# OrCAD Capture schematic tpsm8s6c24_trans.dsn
size E
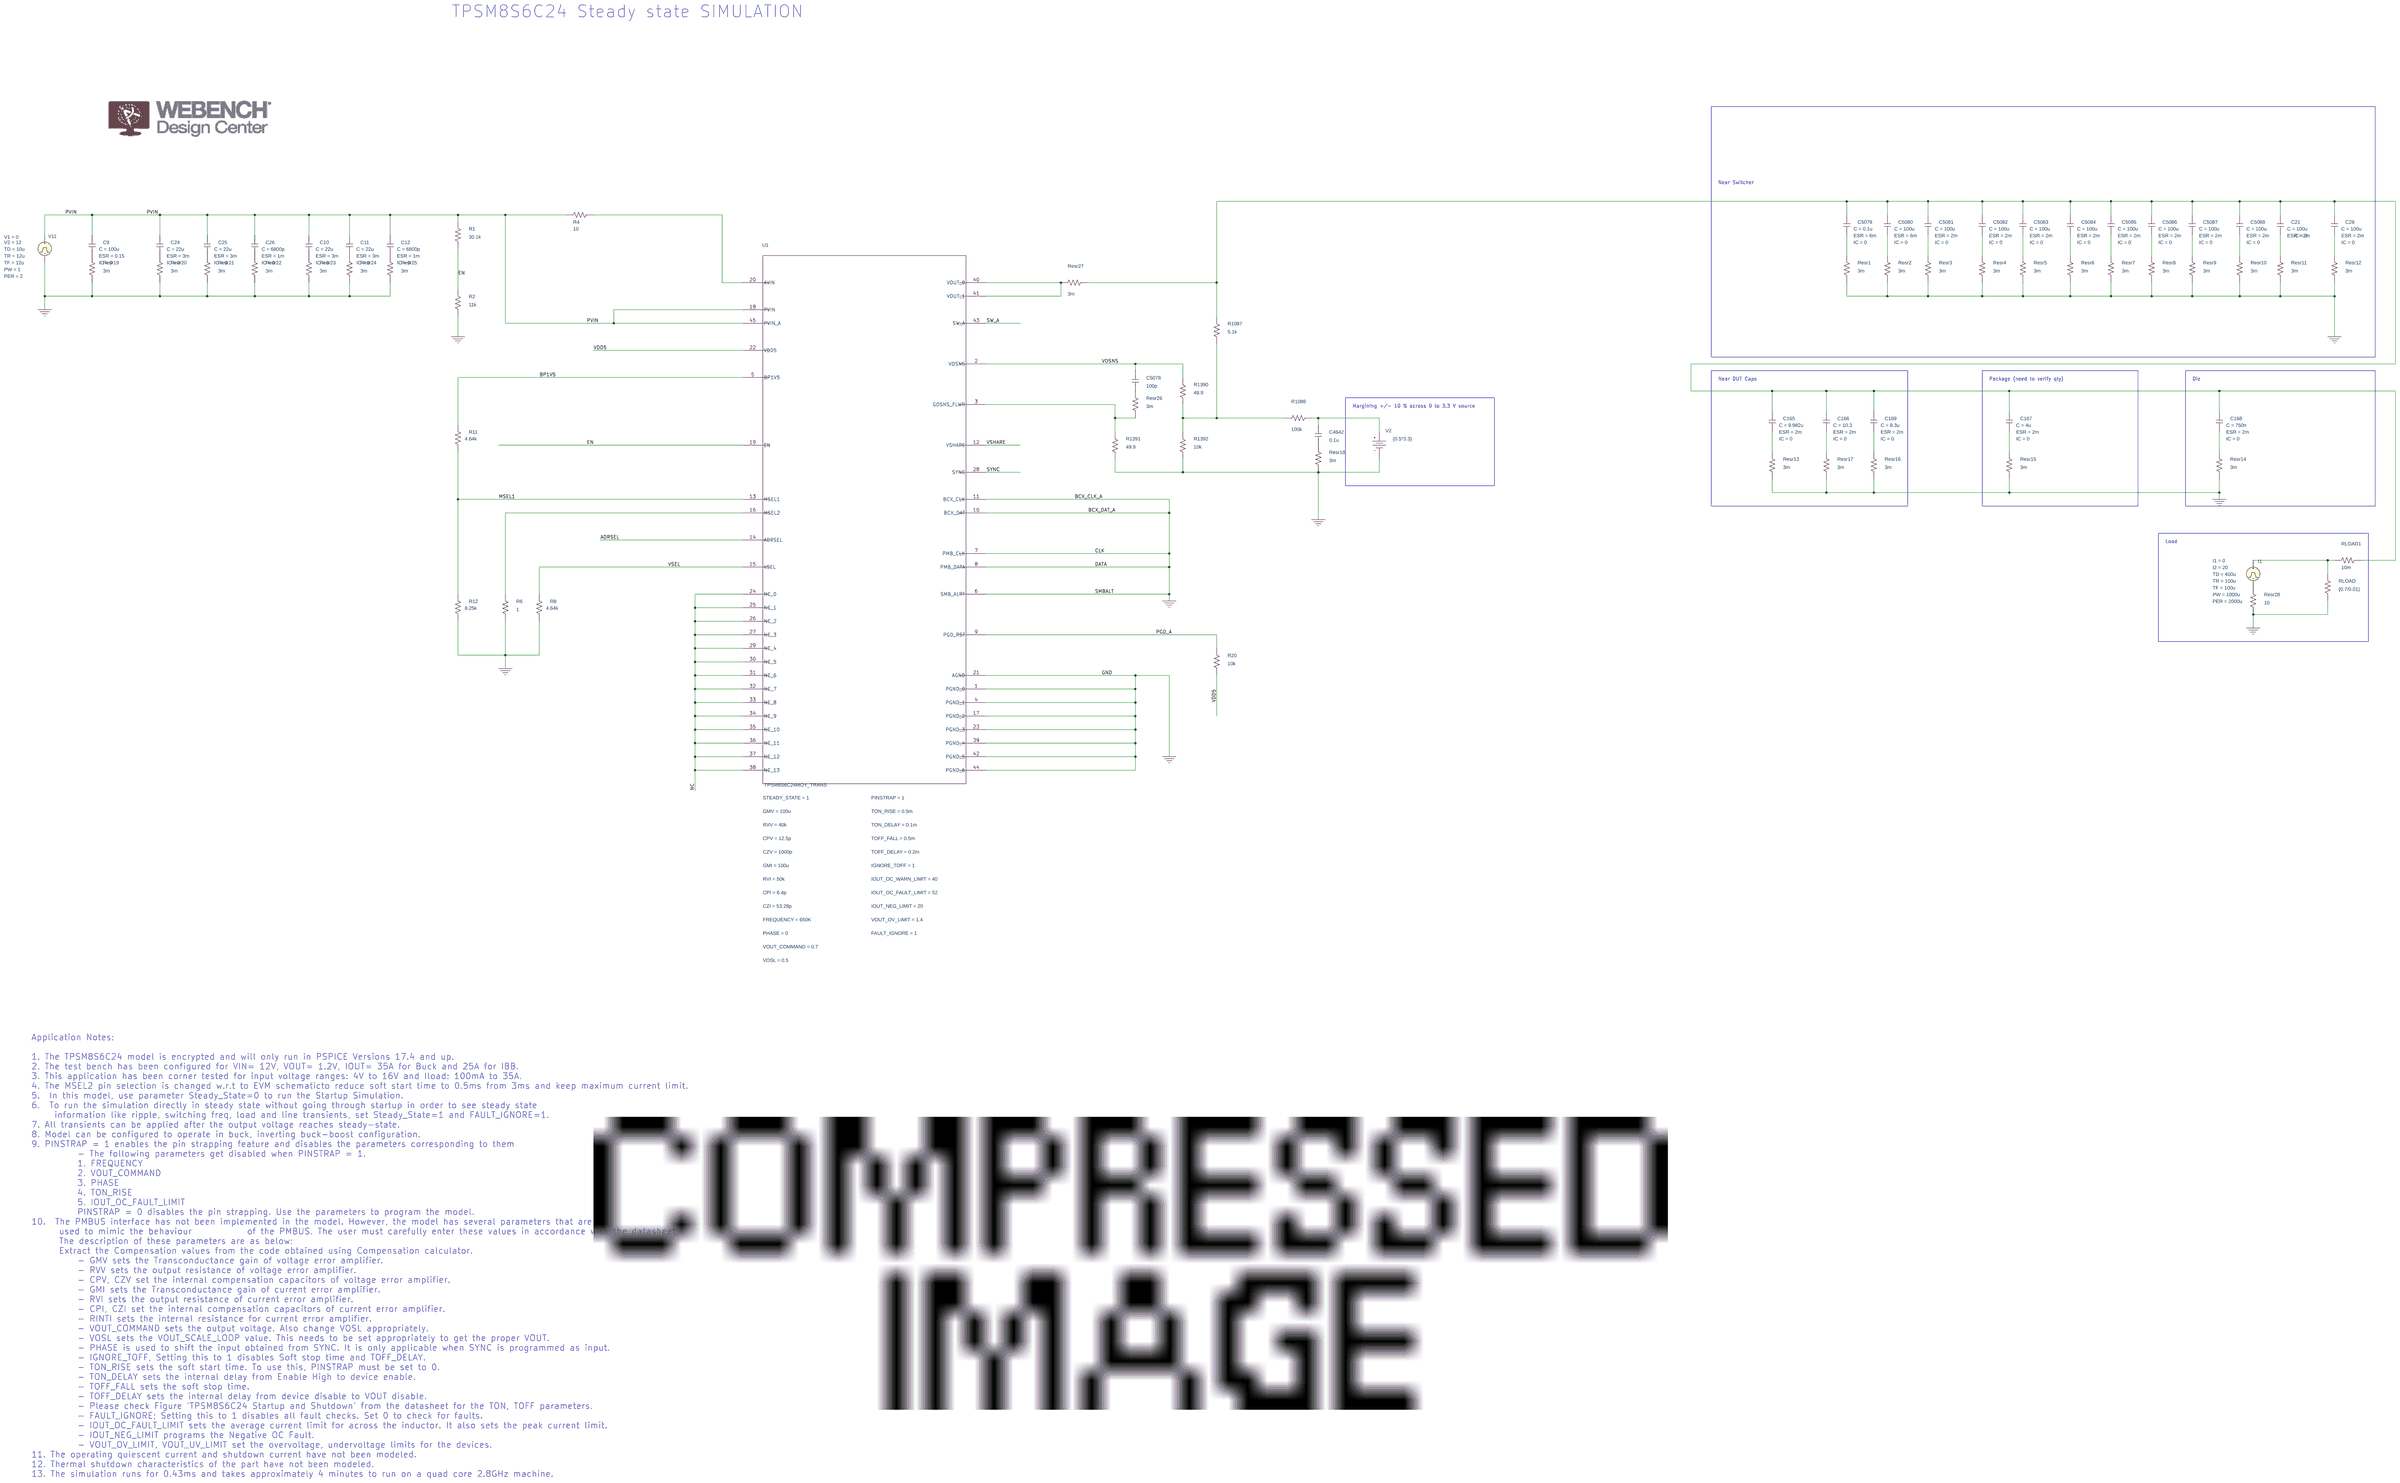
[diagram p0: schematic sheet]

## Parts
C9  100u  [cap196]
C10  100u  [cap196]
C11  100u  [cap196]
C12  100u  [cap196]
C21  100u  [cap196]
C24  100u  [cap196]
C25  100u  [cap196]
C26  100u  [cap196]
C28  100u  [cap196]
C165  100u  [cap196]
C166  100u  [cap196]
C167  100u  [cap196]
C168  100u  [cap196]
C169  100u  [cap196]
C4642  0.1u  [cap196]
C5078  100p  [cap196]
C5079  100u  [cap196]
C5080  100u  [cap196]
C5081  100u  [cap196]
C5082  100u  [cap196]
C5083  100u  [cap196]
C5084  100u  [cap196]
C5085  100u  [cap196]
C5086  100u  [cap196]
C5087  100u  [cap196]
C5088  100u  [cap196]
I1  IPULSE
R1  30.1k  [AXRC05]
R2  11k  [AXRC05]
R4  10  [AXRC05]
R6  1  [AXRC05]
R8  4.64k  [AXRC05]
R11  4.64k  [AXRC05]
R12  8.25k  [AXRC05]
R20  10k  [AXRC05]
R1087  5.1k  [AXRC05]
R1088  100k  [AXRC05]
R1390  49.9  [AXRC05]
R1391  49.9  [AXRC05]
R1392  10k  [AXRC05]
Resr1  3m  [AXRC05]
Resr2  3m  [AXRC05]
Resr3  3m  [AXRC05]
Resr4  3m  [AXRC05]
Resr5  3m  [AXRC05]
Resr6  3m  [AXRC05]
Resr7  3m  [AXRC05]
Resr8  3m  [AXRC05]
Resr9  3m  [AXRC05]
Resr10  3m  [AXRC05]
Resr11  3m  [AXRC05]
Resr12  3m  [AXRC05]
Resr13  3m  [AXRC05]
Resr14  3m  [AXRC05]
Resr15  3m  [AXRC05]
Resr16  3m  [AXRC05]
Resr17  3m  [AXRC05]
Resr18  3m  [AXRC05]
Resr19  3m  [AXRC05]
Resr20  3m  [AXRC05]
Resr21  3m  [AXRC05]
Resr22  3m  [AXRC05]
Resr23  3m  [AXRC05]
Resr24  3m  [AXRC05]
Resr25  3m  [AXRC05]
Resr26  3m  [AXRC05]
Resr27  3m  [AXRC05]
Resr28  10  [AXRC05]
RLOAD  {0.7/0.01}  [AXRC05]
RLOAD1  10m  [AXRC05]
U1  Value  [MOY0045A-MFG]
V2  VDC
V11  VPULSE

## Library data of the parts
C9 = C: ESR: 0.15; IC: 0
C10 C11 C24 C25 = C: C: 22u; ESR: 3m; IC: 0
C12 C26 = C: C: 6800p; ESR: 1m; IC: 0
C21 C28 C5081-C5088 = C: ESR: 2m; IC: 0
C165 = C: C: 9.982u; ESR: 2m; IC: 0
C166 = C: C: 10.3; ESR: 2m; IC: 0
C167 = C: C: 4u; ESR: 2m; IC: 0
C168 = C: C: 750n; ESR: 2m; IC: 0
C169 = C: C: 8.3u; ESR: 2m; IC: 0
C4642 C5078 = C
C5079 = C: C: 0.1u; ESR: 6m; IC: 0
C5080 = C: ESR: 6m; IC: 0
I1 = IPULSE: I1: 0; I2: 20; PER: 2000u; PW: 1000u; TD: 400u; TF: 100u; TR: 100u
R1 R2 R4 R6 R8 R11 R12 R20 R1087 R1088 R1390-R1392 Resr1-Resr28 RLOAD RLOAD1 = R
U1 = TPSM8S6C24SMOY_TRANS: < Value >: TPSM8S6C24MOY_TRANS; CPI: 6.4p; CPV: 12.5p; CSGAIN: 6.155M; CZI: 53.28p; CZV: 1000p; FAULT_IGNORE: 1; FREQUENCY: 650K; GM: 500U; GMI: 100u; GMV: 100u; IGNORE_TOFF: 1; IOUT_NEG_LIMIT: 20; IOUT_OC_FAULT_LIMIT: 52; IOUT_OC_WARN_LIMIT: 40; PHASE: 0; PINSTRAP: 1; PSpiceTemplate: X^@REFDES  %ADRSEL %AGND %AVIN %BCX_CLK %BCX_DAT %BP1V5 %EN %GOSNS_FLWR %MSEL1 %MSEL2 %PGD_RST %PGND_0 %PGND_1 %PGND_2 %PGND_3 %PGND_4 %PGND_5 %PGND_6 %PMB_CLK %PMB_DATA %PVIN %PVIN_A %SMB_ALRT %SW_A %SYNC %VDD5 %VOSNS %VOUT_0 %NC_0 %NC_1 %NC_2 %NC_3 %NC_4 %NC_5 %NC_6 %NC_7 %NC_8 %NC_9 %NC_10 %NC_11 %NC_12 %NC_13 %VOUT_1 %VSEL %VSHARE @MODEL PARAMS: ?CPI|CPI=@CPI||CPI=9.6P| ?CPV|CPV=@CPV||CPV=18.75P| ?CSGAIN|CSGAIN=@CSGAIN||CSGAIN=6.155M| ?CZI|CZI=@CZI||CZI=240P| ?CZV|CZV=@CZV||CZV=750P| ?FAULT_IGNORE|FAULT_IGNORE=@FAULT_IGNORE||FAULT_IGNORE=1| ?FREQUENCY|FREQUENCY=@FREQUENCY||FREQUENCY=550K| ?GM|GM=@GM||GM=500U| ?GMI|GMI=@GMI||GMI=100U| ?GMV|GMV=@GMV||GMV=100U| ?IGNORE_TOFF|IGNORE_TOFF=@IGNORE_TOFF||IGNORE_TOFF=0| ?IOUT_NEG_LIMIT|IOUT_NEG_LIMIT=@IOUT_NEG_LIMIT||IOUT_NEG_LIMIT=52| ?IOUT_OC_FAULT_LIMIT|IOUT_OC_FAULT_LIMIT=@IOUT_OC_FAULT_LIMIT||IOUT_OC_FAULT_LIMIT=52| ?IOUT_OC_WARN_LIMIT|IOUT_OC_WARN_LIMIT=@IOUT_OC_WARN_LIMIT||IOUT_OC_WARN_LIMIT=40| ?PHASE|PHASE=@PHASE||PHASE=0| ?PINSTRAP|PINSTRAP=@PINSTRAP||PINSTRAP=0| ?RINTI|RINTI=@RINTI||RINTI=800K| ?RVI|RVI=@RVI||RVI=40K| ?RVV|RVV=@RVV||RVV=40K| ?STEADY_STATE|STEADY_STATE=@STEADY_STATE||STEADY_STATE=0| ?TOFF_DELAY|TOFF_DELAY=@TOFF_DELAY||TOFF_DELAY=0.2M| ?TOFF_FALL|TOFF_FALL=@TOFF_FALL||TOFF_FALL=0.5| ?TON_DELAY|TON_DELAY=@TON_DELAY||TON_DELAY=0.1M| ?TON_RISE|TON_RISE=@TON_RISE||TON_RISE=0.5M| ?VOSL|VOSL=@VOSL||VOSL=0.5| ?VOUT_COMMAND|VOUT_COMMAND=@VOUT_COMMAND||VOUT_COMMAND=0.8| ?VOUT_OV_LIMIT|VOUT_OV_LIMIT=@VOUT_OV_LIMIT||VOUT_OV_LIMIT=1.4|; RDSHS: 3.2M; RDSLS: 0.85M; RINTI: 800K; RVI: 50k; RVV: 40k; STEADY_STATE: 1; TOFF_DELAY: 0.2m; TOFF_FALL: 0.5m; TON_DELAY: 0.1m; TON_RISE: 0.5m; VOSL: 0.5; VOUT_COMMAND: 0.7; VOUT_OV_LIMIT: 1.4
V2 = VDC: DC: {0.5*3.3}
V11 = VPULSE: PER: 2; PW: 1; TD: 10u; TF: 12u; TR: 12u; V1: 0; V2: 12

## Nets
PVIN: C9.2 C10.2 C11.2 C12.2 C24.2 C25.2 C26.2 R1.2 R4.2 U1.18(PVIN) U1.45(PVIN_A) V11.1(+)
VDD5: R20.1 U1.22(VDD5)
0: R2.1 R6.1 R8.1 R12.1 R1391.2 R1392.2 Resr1.1 Resr2.1 Resr3.1 Resr4.1 Resr5.1 Resr6.1 Resr7.1 Resr8.1 Resr9.1 Resr10.1 Resr11.1 Resr12.1 Resr13.1 Resr14.1 Resr15.1 Resr16.1 Resr17.1 Resr18.1 Resr19.1 Resr20.1 Resr21.1 Resr22.1 Resr23.1 Resr24.1 Resr25.1 Resr28.1 RLOAD.1 U1.1(PGND_0) U1.4(PGND_1) U1.6(SMB_ALRT) U1.7(PMB_CLK) U1.8(PMB_DATA) U1.10(BCX_DAT) U1.11(BCX_CLK) U1.17(PGND_2) U1.21(AGND) U1.23(PGND_3) U1.39(PGND_4) U1.42(PGND_5) U1.44(PGND_6) V2.1(-) V11.2(-)
ADRSEL: U1.14(ADRSEL)
BP1V5: R11.2 U1.5(BP1V5)
EN: R1.1 R2.2 U1.19(EN)
MSEL1: R11.1 R12.2 U1.13(MSEL1)
NC: U1.24(NC_0) U1.25(NC_1) U1.26(NC_2) U1.27(NC_3) U1.29(NC_4) U1.30(NC_5) U1.31(NC_6) U1.32(NC_7) U1.33(NC_8) U1.34(NC_9) U1.35(NC_10) U1.36(NC_11) U1.37(NC_12) U1.38(NC_13)
PGD_A: R20.2 U1.9(PGD_RST)
SW_A: U1.43(SW_A)
SYNC: U1.28(SYNC)
VOSNS: C5078.2 R1390.1 U1.2(VOSNS)
VSEL: R8.2 U1.15(VSEL)
VSHARE: U1.12(VSHARE)
N391398: R4.1 U1.20(AVIN)
N562467: C21.2 C28.2 C165.2 C166.2 C167.2 C168.2 C169.2 C5079.2 C5080.2 C5081.2 C5082.2 C5083.2 C5084.2 C5085.2 C5086.2 C5087.2 C5088.2 R1087.1 Resr27.1 RLOAD1.1
N562511: R1087.2 R1088.1 R1390.2 R1392.1
N562579: R1391.1 Resr26.1 U1.3(GOSNS_FLWR)
N562627: C4642.2 R1088.2 V2.0(+)
N563503: R6.2 U1.16(MSEL2)
N575978: C5080.1 Resr2.2
N575982: C5081.1 Resr3.2
N575986: C5082.1 Resr4.2
N575990: C5083.1 Resr5.2
N575994: C5084.1 Resr6.2
N575998: C5085.1 Resr7.2
N576002: C5086.1 Resr8.2
N576006: C5087.1 Resr9.2
N576010: C5088.1 Resr10.2
N576014: C21.1 Resr11.2
N576252: C165.1 Resr13.2
N576256: C166.1 Resr17.2
N576260: C169.1 Resr16.2
N576264: C167.1 Resr15.2
N576302: I1.1(+) RLOAD.2 RLOAD1.2
N577313: C5079.1 Resr1.2
N588153: C28.1 Resr12.2
N590165: C168.1 Resr14.2
N596103: Resr27.2 U1.40(VOUT_0) U1.41(VOUT_1)
N598308: C10.1 Resr23.2
N598309: C5078.1 Resr26.2
N598310: C11.1 Resr24.2
N598311: C12.1 Resr25.2
N598312: C25.1 Resr21.2
N598313: C9.1 Resr19.2
N598314: C4642.1 Resr18.2
N598315: C26.1 Resr22.2
N598316: C24.1 Resr20.2
N599184: I1.2(-) Resr28.2

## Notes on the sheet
- TPSM8S6C24 Steady state SIMULATION
- Near Switcher
- Near DUT Caps
- Package (need to verify qty)
- Die
- Margining +/- 10 % across 0 to 3.3 V source
- Load
- Application Notes:
  1. The TPSM8S6C24 model is encrypted and will only run in PSPICE Versions 17.4 and up.
  2. The test bench has been configured for VIN= 12V, VOUT= 1.2V, IOUT= 35A for Buck and 25A for IBB.
  3. This application has been corner tested for input voltage ranges: 4V to 16V and Iload: 100mA to 35A.
  4. The MSEL2 pin selection is changed w.r.t to EVM schematicto reduce soft start time to 0.5ms from 3ms and keep maximum current limit.
  5.  In this model, use parameter Steady_State=0 to run the Startup Simulation.
  6.  To run the simulation directly in steady state without going through startup in order to see steady state
       information like ripple, switching freq, load and line transients, set Steady_State=1 and FAULT_IGNORE=1.
  7. All transients can be applied after the output voltage reaches steady-state.
  8. Model can be configured to operate in buck, inverting buck-boost configuration.
  9. PINSTRAP = 1 enables the pin strapping feature and disables the parameters corresponding to them
            - The following parameters get disabled when PINSTRAP = 1.
            1. FREQUENCY
            2. VOUT_COMMAND
            3. PHASE
            4. TON_RISE
            5. IOUT_OC_FAULT_LIMIT
            PINSTRAP = 0 disables the pin strapping. Use the parameters to program the model.
  10.  The PMBUS interface has not been implemented in the model. However, the model has several parameters that are
        used to mimic the behaviour	of the PMBUS. The user must carefully enter these values in accordance with the datasheet.
        The description of these parameters are as below:
        Extract the Compensation values from the code obtained using Compensation calculator.
            - GMV sets the Transconductance gain of voltage error amplifier.
            - RVV sets the output resistance of voltage error amplifier.
            - CPV, CZV set the internal compensation capacitors of voltage error amplifier.
            - GMI sets the Transconductance gain of current error amplifier.
            - RVI sets the output resistance of current error amplifier.
            - CPI, CZI set the internal compensation capacitors of current error amplifier.
            - RINTI sets the internal resistance for current error amplifier.
            - VOUT_COMMAND sets the output voltage. Also change VOSL appropriately.
            - VOSL sets the VOUT_SCALE_LOOP value. This needs to be set appropriately to get the proper VOUT.
            - PHASE is used to shift the input obtained from SYNC. It is only applicable when SYNC is programmed as input.
            - IGNORE_TOFF, Setting this to 1 disables Soft stop time and TOFF_DELAY.
            - TON_RISE sets the soft start time. To use this, PINSTRAP must be set to 0.
            - TON_DELAY sets the internal delay from Enable High to device enable.
            - TOFF_FALL sets the soft stop time.
            - TOFF_DELAY sets the internal delay from device disable to VOUT disable.
            - Please check Figure 'TPSM8S6C24 Startup and Shutdown' from the datasheet for the TON, TOFF parameters.
            - FAULT_IGNORE; Setting this to 1 disables all fault checks. Set 0 to check for faults.
            - IOUT_OC_FAULT_LIMIT sets the average current limit for across the inductor. It also sets the peak current limit.
            - IOUT_NEG_LIMIT programs the Negative OC Fault.
            - VOUT_OV_LIMIT, VOUT_UV_LIMIT set the overvoltage, undervoltage limits for the devices.
  11. The operating quiescent current and shutdown current have not been modeled.
  12. Thermal shutdown characteristics of the part have not been modeled.
  13. The simulation runs for 0.43ms and takes approximately 4 minutes to run on a quad core 2.8GHz machine.
